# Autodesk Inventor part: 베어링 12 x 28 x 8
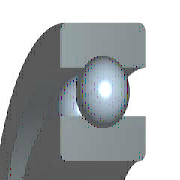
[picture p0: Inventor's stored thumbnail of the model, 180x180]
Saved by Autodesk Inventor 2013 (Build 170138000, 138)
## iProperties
IsCustomPart: 1
Created: 2012-02
Part Number: 베어링 12 x 28 x 8
Material: 강철, 연강
Description: 깊은 그루브 볼 베어링
Document SubType Name: Modeling
Standard: KS B 2023
Designer: mduedu
Standards Organization: KS
Language: ko-KR
Size Designation: 6001 - 12 x 28 x 8
Categories: <MemberInstance><Categories><Category DisplayName="샤프트 부품" InternalName="7f7aeb1f-a693-4053-b835-cee3144e0d98" Mnemonic="SHFT"><Category DisplayName="베어링" Inter
Density: 7.86 g/cm^3
Mass: 21.4854 g
Surface Area: 31.1809 cm^2
Volume: 2.73351 cm^3
Author: mduedu
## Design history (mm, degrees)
sketch "스케치" dims "d0" = 4.16 (= -0.26 x WD + 0.26 x BD)
  geometry: L1 (1.92, 10)-(6.08, 10); L2 (4, 10)-(4, 7.92); L3 (4, 10)-(4, 12.08); L4 (2.454, 8.608)-(0, 8.608); L5 (0, 6)-(8, 6); L6 (2.454, 11.392)-(0, 11.392); L7 (0, 14)-(8, 14); L8 (8, 6)-(8, 8.608); L9 (5.546, 8.608)-(8, 8.608); L10 (5.546, 11.392)-(8, 11.392); L11 (8, 14)-(8, 11.392); L12 (-1.4, 0)-(8.4, 0) reference; L13 (0, -0.3)-(0, 5.3) reference
  constraints: 22 end point, 4 point on line, 2 collinear, 2 perpendicular, 2 symmetric about line, 1 midpoint, 1 parallel, 14 other
  dimensions: "d9" = 12 diameter of L5 L12 (= WD); "d11" = 28 diameter of L7 L12 (= BD); "d12" = 8 distance between parallel lines of L8 L13 (= KB); "d13" = 17.216 diameter of L9 L12 (= 0.326 x BD + 0.674 x WD)
revolve "본체" stored, may be unused: angle "d6" = 90 deg
revolve "볼" stored, may be unused: angle "d7" = 90 deg
pattern_circular "IDS_ARRAYBALL[SIMPL:T]" dims angle "d3" = 360 deg
body "Solid1"
fillet "모깎기1" dims "d1" = 0.3 (= KRS)
other parameters: "WD" = 12 [user parameter; used in 5 equation terms], "BD" = 28 [user parameter; used in 5 equation terms], "KB" = 8 [user parameter; used in 1 equation term], "KRS" = 0.3 [user parameter; used in 1 equation term], "d4" = 0, "d5" = 0, "d8" = 0, "d14" = 0, "d15" = 0, "BBA" = 0 [user parameter], "BC0" = 2360000 [user parameter], "BC" = 5070000 [user parameter], "BR" = 14 (= 0.5 x BD) [user parameter], "WR" = 6 (= 0.5 x WD) [user parameter]
